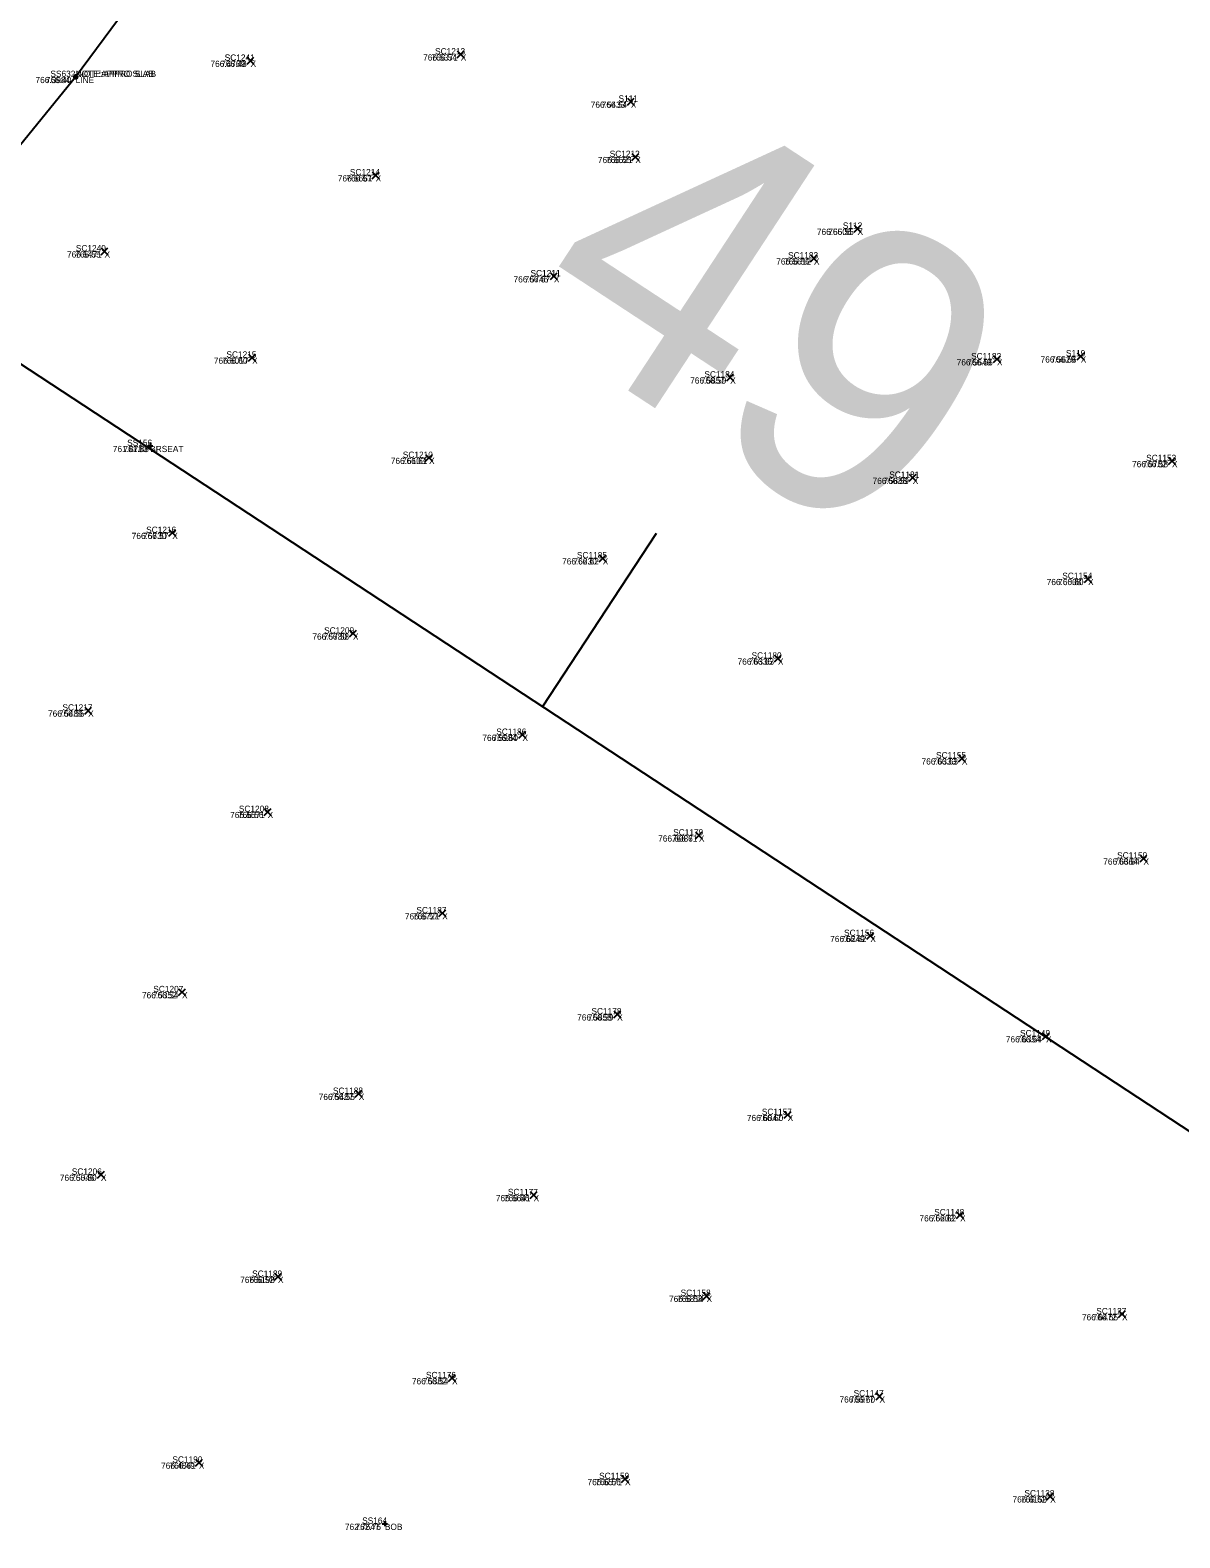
# Model space of a CAD drawing. Extents: x 1845019 to 1877956, y 680444 to 701081.
# Drawn here: x 1857559.96 to 1857571.05, y 694336.67 to 694351.2 of the extents above; entities that cross this region are included whole.
import ezdxf

# ---------------------------------------------------------------- set-up
doc = ezdxf.new("R2010")
doc.units = 0
for name, color, linetype in [('BR_X_SV_Beam_Seat', 7, 'Continuous'), ('BR_X_SV_Bottom_of_Beam_Text', 7, 'Continuous'), ('Default', 7, 'Continuous'), ('SV_X_CL_Survey_20', 7, 'Continuous'), ('SV_X_Random_Point', 7, 'Continuous'), ('SV_X_Shot_Marker', 7, 'Continuous'), ('SV_X_Text_Comment', 7, 'Continuous'), ('SV_X_Text_Description', 7, 'Continuous'), ('SV_X_Text_Elevation', 7, 'Continuous'), ('SV_X_Text_Name', 7, 'Continuous')]:
    doc.layers.add(name, color=color, linetype=linetype)

msp = doc.modelspace()

# ---------------------------------------------------------------- linework, layer by layer
at = {"layer": 'BR_X_SV_Beam_Seat'}
for p, q in [((1857561.092, 694347.198), (1857561.142, 694347.198)), ((1857561.092, 694347.198), (1857561.142, 694347.198)), ((1857561.117, 694347.223), (1857561.117, 694347.173)), ((1857561.117, 694347.223), (1857561.117, 694347.173)), ((1857561.117, 694347.198), (1857561.117, 694347.198)), ((1857561.117, 694347.198), (1857561.117, 694347.198))]:
    msp.add_line(p, q, dxfattribs=at)
at = {"layer": 'BR_X_SV_Bottom_of_Beam_Text'}
for p, q in [((1857563.355, 694336.811), (1857563.405, 694336.811)), ((1857563.355, 694336.811), (1857563.405, 694336.811)), ((1857563.38, 694336.836), (1857563.38, 694336.786)), ((1857563.38, 694336.836), (1857563.38, 694336.786)), ((1857563.38, 694336.811), (1857563.38, 694336.811)), ((1857563.38, 694336.811), (1857563.38, 694336.811))]:
    msp.add_line(p, q, dxfattribs=at)
at = {"layer": 'Default'}
msp.add_lwpolyline([(1857529.179, 694350.113), (1857549.875, 694336.9), (1857553.678, 694341.573), (1857557.829, 694347.6), (1857560.398, 694350.754), (1857568.363, 694361.498), (1857547.247, 694374.307), (1857542.393, 694367.435), (1857538.138, 694361.818), (1857529.244, 694350.474)], dxfattribs=at)
msp.add_lwpolyline([(1857529.179, 694350.113), (1857549.875, 694336.9), (1857553.678, 694341.573), (1857557.829, 694347.6), (1857560.398, 694350.754), (1857568.363, 694361.498), (1857547.247, 694374.307), (1857542.393, 694367.435), (1857538.138, 694361.818), (1857529.244, 694350.474)], dxfattribs=at)
at = {"layer": 'SV_X_CL_Survey_20'}
for p, q in [((1856038.267, 695346.314), (1858797.327, 693536.085)), ((1857564.901, 694344.684), (1857565.998, 694346.357))]:
    msp.add_line(p, q, dxfattribs=at)
at = {"layer": 'SV_X_Random_Point'}
for p, q in [((1857564.078, 694350.937), (1857564.145, 694351.004)), ((1857564.078, 694351.004), (1857564.145, 694350.937)), ((1857564.078, 694350.937), (1857564.145, 694351.004)), ((1857564.078, 694351.004), (1857564.145, 694350.937)), ((1857562.052, 694350.877), (1857562.118, 694350.943)), ((1857562.052, 694350.943), (1857562.118, 694350.877)), ((1857562.052, 694350.877), (1857562.118, 694350.943)), ((1857562.052, 694350.943), (1857562.118, 694350.877)), ((1857565.719, 694350.482), (1857565.785, 694350.549)), ((1857565.719, 694350.549), (1857565.785, 694350.482)), ((1857565.719, 694350.482), (1857565.785, 694350.549)), ((1857565.719, 694350.549), (1857565.785, 694350.482)), ((1857565.762, 694349.949), (1857565.829, 694350.016)), ((1857565.762, 694350.016), (1857565.829, 694349.949)), ((1857565.762, 694349.949), (1857565.829, 694350.016)), ((1857565.762, 694350.016), (1857565.829, 694349.949)), ((1857563.257, 694349.773), (1857563.324, 694349.839)), ((1857563.257, 694349.839), (1857563.324, 694349.773)), ((1857563.257, 694349.773), (1857563.324, 694349.839)), ((1857563.257, 694349.839), (1857563.324, 694349.773)), ((1857567.905, 694349.258), (1857567.971, 694349.325)), ((1857567.905, 694349.325), (1857567.971, 694349.258)), ((1857567.905, 694349.258), (1857567.971, 694349.325)), ((1857567.905, 694349.325), (1857567.971, 694349.258)), ((1857560.644, 694349.039), (1857560.71, 694349.106)), ((1857560.644, 694349.106), (1857560.71, 694349.039)), ((1857560.644, 694349.039), (1857560.71, 694349.106)), ((1857560.644, 694349.106), (1857560.71, 694349.039)), ((1857567.483, 694348.972), (1857567.55, 694349.038)), ((1857567.483, 694349.038), (1857567.55, 694348.972)), ((1857567.483, 694348.972), (1857567.55, 694349.038)), ((1857567.483, 694349.038), (1857567.55, 694348.972)), ((1857564.976, 694348.8), (1857565.043, 694348.867)), ((1857564.976, 694348.867), (1857565.043, 694348.8)), ((1857564.976, 694348.8), (1857565.043, 694348.867)), ((1857564.976, 694348.867), (1857565.043, 694348.8)), ((1857562.066, 694348.015), (1857562.133, 694348.082)), ((1857562.066, 694348.082), (1857562.133, 694348.015)), ((1857562.066, 694348.015), (1857562.133, 694348.082)), ((1857562.066, 694348.082), (1857562.133, 694348.015)), ((1857569.249, 694348), (1857569.315, 694348.067)), ((1857569.249, 694348.067), (1857569.315, 694348)), ((1857569.249, 694348), (1857569.315, 694348.067)), ((1857569.249, 694348.067), (1857569.315, 694348)), ((1857570.056, 694348.028), (1857570.123, 694348.094)), ((1857570.056, 694348.094), (1857570.123, 694348.028)), ((1857570.056, 694348.028), (1857570.123, 694348.094)), ((1857570.056, 694348.094), (1857570.123, 694348.028)), ((1857566.677, 694347.825), (1857566.743, 694347.891)), ((1857566.677, 694347.891), (1857566.743, 694347.825)), ((1857566.677, 694347.825), (1857566.743, 694347.891)), ((1857566.677, 694347.891), (1857566.743, 694347.825)), ((1857563.772, 694347.049), (1857563.839, 694347.116)), ((1857563.772, 694347.116), (1857563.839, 694347.049)), ((1857563.772, 694347.049), (1857563.839, 694347.116)), ((1857563.772, 694347.116), (1857563.839, 694347.049)), ((1857570.937, 694347.019), (1857571.003, 694347.085)), ((1857570.937, 694347.085), (1857571.003, 694347.019)), ((1857570.937, 694347.019), (1857571.003, 694347.085)), ((1857570.937, 694347.085), (1857571.003, 694347.019)), ((1857568.436, 694346.857), (1857568.503, 694346.924)), ((1857568.436, 694346.924), (1857568.503, 694346.857)), ((1857568.436, 694346.857), (1857568.503, 694346.924)), ((1857568.436, 694346.924), (1857568.503, 694346.857)), ((1857561.296, 694346.327), (1857561.363, 694346.393)), ((1857561.296, 694346.393), (1857561.363, 694346.327)), ((1857561.296, 694346.327), (1857561.363, 694346.393)), ((1857561.296, 694346.393), (1857561.363, 694346.327)), ((1857565.448, 694346.081), (1857565.514, 694346.148)), ((1857565.448, 694346.148), (1857565.514, 694346.081)), ((1857565.448, 694346.081), (1857565.514, 694346.148)), ((1857565.448, 694346.148), (1857565.514, 694346.081)), ((1857570.127, 694345.882), (1857570.194, 694345.949)), ((1857570.127, 694345.949), (1857570.194, 694345.882)), ((1857570.127, 694345.882), (1857570.194, 694345.949)), ((1857570.127, 694345.949), (1857570.194, 694345.882)), ((1857563.038, 694345.357), (1857563.105, 694345.423)), ((1857563.038, 694345.423), (1857563.105, 694345.357)), ((1857563.038, 694345.357), (1857563.105, 694345.423)), ((1857563.038, 694345.423), (1857563.105, 694345.357)), ((1857567.136, 694345.116), (1857567.203, 694345.182)), ((1857567.136, 694345.182), (1857567.203, 694345.116)), ((1857567.136, 694345.116), (1857567.203, 694345.182)), ((1857567.136, 694345.182), (1857567.203, 694345.116)), ((1857560.486, 694344.614), (1857560.552, 694344.681)), ((1857560.486, 694344.681), (1857560.552, 694344.614)), ((1857560.486, 694344.614), (1857560.552, 694344.681)), ((1857560.486, 694344.681), (1857560.552, 694344.614)), ((1857564.673, 694344.381), (1857564.74, 694344.447)), ((1857564.673, 694344.447), (1857564.74, 694344.381)), ((1857564.673, 694344.381), (1857564.74, 694344.447)), ((1857564.673, 694344.447), (1857564.74, 694344.381)), ((1857568.91, 694344.154), (1857568.977, 694344.221)), ((1857568.91, 694344.221), (1857568.977, 694344.154)), ((1857568.91, 694344.154), (1857568.977, 694344.221)), ((1857568.91, 694344.221), (1857568.977, 694344.154)), ((1857562.216, 694343.637), (1857562.283, 694343.704)), ((1857562.216, 694343.704), (1857562.283, 694343.637)), ((1857562.216, 694343.637), (1857562.283, 694343.704)), ((1857562.216, 694343.704), (1857562.283, 694343.637)), ((1857566.375, 694343.411), (1857566.441, 694343.478)), ((1857566.375, 694343.478), (1857566.441, 694343.411)), ((1857566.375, 694343.411), (1857566.441, 694343.478)), ((1857566.375, 694343.478), (1857566.441, 694343.411)), ((1857570.662, 694343.189), (1857570.729, 694343.255)), ((1857570.662, 694343.255), (1857570.729, 694343.189)), ((1857570.662, 694343.189), (1857570.729, 694343.255)), ((1857570.662, 694343.255), (1857570.729, 694343.189)), ((1857563.9, 694342.661), (1857563.967, 694342.727)), ((1857563.9, 694342.727), (1857563.967, 694342.661)), ((1857563.9, 694342.661), (1857563.967, 694342.727)), ((1857563.9, 694342.727), (1857563.967, 694342.661)), ((1857568.027, 694342.443), (1857568.094, 694342.509)), ((1857568.027, 694342.509), (1857568.094, 694342.443)), ((1857568.027, 694342.443), (1857568.094, 694342.509)), ((1857568.027, 694342.509), (1857568.094, 694342.443)), ((1857561.391, 694341.901), (1857561.458, 694341.967)), ((1857561.391, 694341.967), (1857561.458, 694341.901)), ((1857561.391, 694341.901), (1857561.458, 694341.967)), ((1857561.391, 694341.967), (1857561.458, 694341.901)), ((1857565.587, 694341.687), (1857565.654, 694341.753)), ((1857565.587, 694341.753), (1857565.654, 694341.687)), ((1857565.587, 694341.687), (1857565.654, 694341.753)), ((1857565.587, 694341.753), (1857565.654, 694341.687)), ((1857569.722, 694341.476), (1857569.788, 694341.543)), ((1857569.722, 694341.543), (1857569.788, 694341.476)), ((1857569.722, 694341.476), (1857569.788, 694341.543)), ((1857569.722, 694341.543), (1857569.788, 694341.476)), ((1857563.095, 694340.921), (1857563.161, 694340.988)), ((1857563.095, 694340.988), (1857563.161, 694340.921)), ((1857563.095, 694340.921), (1857563.161, 694340.988)), ((1857563.095, 694340.988), (1857563.161, 694340.921)), ((1857567.231, 694340.718), (1857567.298, 694340.784)), ((1857567.231, 694340.784), (1857567.298, 694340.718)), ((1857567.231, 694340.718), (1857567.298, 694340.784)), ((1857567.231, 694340.784), (1857567.298, 694340.718)), ((1857560.609, 694340.141), (1857560.675, 694340.208)), ((1857560.609, 694340.208), (1857560.675, 694340.141)), ((1857560.609, 694340.141), (1857560.675, 694340.208)), ((1857560.609, 694340.208), (1857560.675, 694340.141)), ((1857564.781, 694339.945), (1857564.848, 694340.012)), ((1857564.781, 694340.012), (1857564.848, 694339.945)), ((1857564.781, 694339.945), (1857564.848, 694340.012)), ((1857564.781, 694340.012), (1857564.848, 694339.945)), ((1857568.893, 694339.751), (1857568.96, 694339.817)), ((1857568.893, 694339.817), (1857568.96, 694339.751)), ((1857568.893, 694339.751), (1857568.96, 694339.817)), ((1857568.893, 694339.817), (1857568.96, 694339.751)), ((1857562.316, 694339.158), (1857562.382, 694339.225)), ((1857562.316, 694339.225), (1857562.382, 694339.158)), ((1857562.316, 694339.158), (1857562.382, 694339.225)), ((1857562.316, 694339.225), (1857562.382, 694339.158)), ((1857566.448, 694338.973), (1857566.515, 694339.04)), ((1857566.448, 694339.04), (1857566.515, 694338.973)), ((1857566.448, 694338.973), (1857566.515, 694339.04)), ((1857566.448, 694339.04), (1857566.515, 694338.973)), ((1857570.454, 694338.797), (1857570.521, 694338.864)), ((1857570.454, 694338.864), (1857570.521, 694338.797)), ((1857570.454, 694338.797), (1857570.521, 694338.864)), ((1857570.454, 694338.864), (1857570.521, 694338.797)), ((1857563.994, 694338.181), (1857564.061, 694338.248)), ((1857563.994, 694338.248), (1857564.061, 694338.181)), ((1857563.994, 694338.181), (1857564.061, 694338.248)), ((1857563.994, 694338.248), (1857564.061, 694338.181)), ((1857568.116, 694338.004), (1857568.183, 694338.071)), ((1857568.116, 694338.071), (1857568.183, 694338.004)), ((1857568.116, 694338.004), (1857568.183, 694338.071)), ((1857568.116, 694338.071), (1857568.183, 694338.004)), ((1857561.553, 694337.366), (1857561.62, 694337.433)), ((1857561.553, 694337.433), (1857561.62, 694337.366)), ((1857561.553, 694337.366), (1857561.62, 694337.433)), ((1857561.553, 694337.433), (1857561.62, 694337.366)), ((1857565.662, 694337.209), (1857565.729, 694337.276)), ((1857565.662, 694337.276), (1857565.729, 694337.209)), ((1857565.662, 694337.209), (1857565.729, 694337.276)), ((1857565.662, 694337.276), (1857565.729, 694337.209)), ((1857569.762, 694337.041), (1857569.829, 694337.108)), ((1857569.762, 694337.108), (1857569.829, 694337.041)), ((1857569.762, 694337.041), (1857569.829, 694337.108)), ((1857569.762, 694337.108), (1857569.829, 694337.041))]:
    msp.add_line(p, q, dxfattribs=at)
at = {"layer": 'SV_X_Shot_Marker'}
for p, q in [((1857560.373, 694350.754), (1857560.423, 694350.754)), ((1857560.379, 694350.77), (1857560.418, 694350.738)), ((1857560.383, 694350.734), (1857560.414, 694350.773)), ((1857560.398, 694350.779), (1857560.398, 694350.729)), ((1857560.398, 694350.754), (1857560.398, 694350.754)), ((1857560.398, 694350.754), (1857560.398, 694350.754))]:
    msp.add_line(p, q, dxfattribs=at)

# ---------------------------------------------------------------- texts
at = {"layer": 'BR_X_SV_Beam_Seat'}
for s, p in [('761.8783', (1857560.757, 694347.138)), ('761.88', (1857560.859, 694347.138)), ('SS156', (1857560.895, 694347.198)), ('SS156', (1857560.895, 694347.198)), ('BRSEAT', (1857561.117, 694347.138))]:
    msp.add_text(s, height=0.06, dxfattribs=at).set_placement(p)
at = {"layer": 'BR_X_SV_Bottom_of_Beam_Text'}
for s, p in [('762.7647', (1857562.995, 694336.751)), ('762.76', (1857563.097, 694336.751)), ('SS164', (1857563.161, 694336.811)), ('SS164', (1857563.161, 694336.811)), ('BOB', (1857563.38, 694336.751))]:
    msp.add_text(s, height=0.06, dxfattribs=at).set_placement(p)
at = {"layer": 'SV_X_CL_Survey_20'}
msp.add_text('49', height=2.8, rotation=326.731, dxfattribs=at).set_placement((1857564.639, 694348.444))
at = {"layer": 'SV_X_Text_Comment'}
for s, p in [('X', (1857564.112, 694350.911)), ('X', (1857562.085, 694350.85)), ('LINE', (1857560.398, 694350.694)), ('X', (1857565.752, 694350.456)), ('X', (1857565.795, 694349.923)), ('X', (1857563.291, 694349.746)), ('X', (1857567.938, 694349.231)), ('X', (1857560.677, 694349.013)), ('X', (1857567.517, 694348.945)), ('X', (1857565.01, 694348.773)), ('X', (1857562.1, 694347.989)), ('X', (1857569.282, 694347.973)), ('X', (1857570.09, 694348.001)), ('X', (1857566.71, 694347.798)), ('X', (1857563.806, 694347.023)), ('X', (1857570.97, 694346.992)), ('X', (1857568.47, 694346.831)), ('X', (1857561.33, 694346.3)), ('X', (1857565.481, 694346.055)), ('X', (1857570.161, 694345.856)), ('X', (1857563.072, 694345.33)), ('X', (1857567.17, 694345.089)), ('X', (1857560.519, 694344.588)), ('X', (1857564.707, 694344.354)), ('X', (1857568.944, 694344.127)), ('X', (1857562.25, 694343.611)), ('X', (1857566.408, 694343.384)), ('X', (1857570.695, 694343.162)), ('X', (1857563.933, 694342.634)), ('X', (1857568.061, 694342.416)), ('X', (1857561.424, 694341.874)), ('X', (1857565.62, 694341.66)), ('X', (1857569.755, 694341.449)), ('X', (1857563.128, 694340.894)), ('X', (1857567.264, 694340.691)), ('X', (1857560.642, 694340.115)), ('X', (1857564.814, 694339.918)), ('X', (1857568.927, 694339.724)), ('X', (1857562.349, 694339.131)), ('X', (1857566.482, 694338.947)), ('X', (1857570.488, 694338.77)), ('X', (1857564.028, 694338.154)), ('X', (1857568.15, 694337.978)), ('X', (1857561.586, 694337.34)), ('X', (1857565.696, 694337.182)), ('X', (1857569.796, 694337.015))]:
    msp.add_text(s, height=0.06, dxfattribs=at).set_placement(p)
at = {"layer": 'SV_X_Text_Description'}
for s in ['NOTE:APPRO SLAB', ' NOTE:APPRO SLAB']:
    msp.add_text(s, height=0.06, dxfattribs=at).set_placement((1857560.398, 694350.754))
at = {"layer": 'SV_X_Text_Elevation'}
for s, p in [('766.5371', (1857563.749, 694350.911)), ('766.54', (1857563.83, 694350.911)), ('766.4769', (1857561.698, 694350.85)), ('766.48', (1857561.802, 694350.85)), ('766.3984', (1857560.011, 694350.694)), ('766.40', (1857560.111, 694350.694)), ('766.5433', (1857565.365, 694350.456)), ('766.54', (1857565.471, 694350.456)), ('766.5521', (1857565.434, 694349.923)), ('766.55', (1857565.513, 694349.923)), ('766.5661', (1857562.926, 694349.746)), ('766.57', (1857563.009, 694349.746)), ('766.5508', (1857567.546, 694349.231)), ('766.55', (1857567.656, 694349.231)), ('766.5471', (1857560.315, 694349.013)), ('766.55', (1857560.395, 694349.013)), ('766.5612', (1857567.154, 694348.945)), ('766.56', (1857567.231, 694348.945)), ('766.5746', (1857564.621, 694348.773)), ('766.57', (1857564.728, 694348.773)), ('766.6017', (1857561.731, 694347.989)), ('766.60', (1857561.811, 694347.989)), ('766.5649', (1857568.894, 694347.973)), ('766.56', (1857568.996, 694347.973)), ('766.5629', (1857569.703, 694348.001)), ('766.56', (1857569.804, 694348.001)), ('766.5857', (1857566.324, 694347.798)), ('766.59', (1857566.427, 694347.798)), ('766.6103', (1857563.437, 694347.023)), ('766.61', (1857563.545, 694347.023)), ('766.5782', (1857570.585, 694346.992)), ('766.58', (1857570.687, 694346.992)), ('766.5888', (1857568.083, 694346.831)), ('766.59', (1857568.187, 694346.831)), ('766.5730', (1857560.939, 694346.3)), ('766.57', (1857561.048, 694346.3)), ('766.6230', (1857565.089, 694346.055)), ('766.62', (1857565.198, 694346.055)), ('766.6008', (1857569.762, 694345.856)), ('766.60', (1857569.872, 694345.856)), ('766.5780', (1857562.681, 694345.33)), ('766.58', (1857562.789, 694345.33)), ('766.6335', (1857566.781, 694345.089)), ('766.63', (1857566.887, 694345.089)), ('766.5489', (1857560.132, 694344.588)), ('766.55', (1857560.237, 694344.588)), ('766.5984', (1857564.32, 694344.354)), ('766.60', (1857564.418, 694344.354)), ('766.6333', (1857568.555, 694344.127)), ('766.63', (1857568.661, 694344.127)), ('766.5571', (1857561.888, 694343.611)), ('766.56', (1857561.964, 694343.611)), ('766.6087', (1857566.015, 694343.384)), ('766.61', (1857566.148, 694343.384)), ('766.6364', (1857570.307, 694343.162)), ('766.64', (1857570.413, 694343.162)), ('766.5721', (1857563.573, 694342.634)), ('766.57', (1857563.651, 694342.634)), ('766.6249', (1857567.674, 694342.416)), ('766.62', (1857567.778, 694342.416)), ('766.5352', (1857561.038, 694341.874)), ('766.54', (1857561.143, 694341.874)), ('766.5858', (1857565.234, 694341.66)), ('766.59', (1857565.338, 694341.66)), ('766.6354', (1857569.368, 694341.449)), ('766.64', (1857569.472, 694341.449)), ('766.5487', (1857562.742, 694340.894)), ('766.55', (1857562.846, 694340.894)), ('766.6047', (1857566.871, 694340.691)), ('766.60', (1857566.976, 694340.691)), ('766.5046', (1857560.246, 694340.115)), ('766.50', (1857560.355, 694340.115)), ('766.5641', (1857564.45, 694339.918)), ('766.56', (1857564.528, 694339.918)), ('766.6203', (1857568.535, 694339.724)), ('766.62', (1857568.644, 694339.724)), ('766.5198', (1857561.985, 694339.131)), ('766.52', (1857562.067, 694339.131)), ('766.5814', (1857566.12, 694338.947)), ('766.58', (1857566.199, 694338.947)), ('766.6472', (1857570.102, 694338.77)), ('766.65', (1857570.205, 694338.77)), ('766.5382', (1857563.641, 694338.154)), ('766.54', (1857563.746, 694338.154)), ('766.5977', (1857567.764, 694337.978)), ('766.60', (1857567.862, 694337.978)), ('766.4861', (1857561.222, 694337.34)), ('766.49', (1857561.303, 694337.34)), ('766.5571', (1857565.334, 694337.182)), ('766.56', (1857565.41, 694337.182)), ('766.6159', (1857569.432, 694337.015)), ('766.62', (1857569.513, 694337.015))]:
    msp.add_text(s, height=0.06, dxfattribs=at).set_placement(p)
at = {"layer": 'SV_X_Text_Name'}
for s, p in [('SC1241', (1857561.835, 694350.91)), ('SC1241', (1857561.836, 694350.91)), ('SC1213', (1857563.864, 694350.971)), ('SC1213', (1857563.864, 694350.971)), ('SS632', (1857560.155, 694350.754)), ('SS632', (1857560.155, 694350.754)), ('S111', (1857565.633, 694350.516)), ('S111', (1857565.633, 694350.516)), ('SC1212', (1857565.548, 694349.983)), ('SC1212', (1857565.548, 694349.983)), ('SC1214', (1857563.043, 694349.806)), ('SC1214', (1857563.043, 694349.806)), ('S112', (1857567.796, 694349.291)), ('S112', (1857567.796, 694349.291)), ('SC1240', (1857560.4, 694349.073)), ('SC1240', (1857560.4, 694349.073)), ('SC1183', (1857567.268, 694349.005)), ('SC1183', (1857567.268, 694349.005)), ('SC1211', (1857564.784, 694348.833)), ('SC1211', (1857564.785, 694348.833)), ('SC1215', (1857561.852, 694348.049)), ('SC1215', (1857561.852, 694348.049)), ('SC1182', (1857569.033, 694348.033)), ('SC1182', (1857569.033, 694348.033)), ('S119', (1857569.947, 694348.061)), ('S119', (1857569.947, 694348.061)), ('SC1184', (1857566.461, 694347.858)), ('SC1184', (1857566.461, 694347.858)), ('SC1210', (1857563.553, 694347.083)), ('SC1210', (1857563.553, 694347.083)), ('SC1153', (1857570.721, 694347.052)), ('SC1153', (1857570.721, 694347.052)), ('SC1181', (1857568.243, 694346.891)), ('SC1181', (1857568.244, 694346.891)), ('SC1216', (1857561.078, 694346.36)), ('SC1216', (1857561.078, 694346.36)), ('SC1185', (1857565.232, 694346.115)), ('SC1185', (1857565.232, 694346.115)), ('SC1154', (1857569.912, 694345.916)), ('SC1154', (1857569.912, 694345.916)), ('SC1209', (1857562.794, 694345.39)), ('SC1209', (1857562.794, 694345.39)), ('SC1180', (1857566.916, 694345.149)), ('SC1180', (1857566.916, 694345.149)), ('SC1217', (1857560.271, 694344.648)), ('SC1217', (1857560.271, 694344.648)), ('SC1186', (1857564.454, 694344.414)), ('SC1186', (1857564.454, 694344.414)), ('SC1155', (1857568.695, 694344.187)), ('SC1155', (1857568.695, 694344.187)), ('SC1208', (1857561.972, 694343.671)), ('SC1208', (1857561.972, 694343.671)), ('SC1179', (1857566.16, 694343.444)), ('SC1179', (1857566.16, 694343.444)), ('SC1150', (1857570.441, 694343.222)), ('SC1150', (1857570.441, 694343.222)), ('SC1187', (1857563.684, 694342.694)), ('SC1187', (1857563.684, 694342.694)), ('SC1156', (1857567.808, 694342.476)), ('SC1156', (1857567.808, 694342.476)), ('SC1207', (1857561.147, 694341.934)), ('SC1207', (1857561.147, 694341.934)), ('SC1178', (1857565.372, 694341.72)), ('SC1178', (1857565.372, 694341.72)), ('SC1149', (1857569.505, 694341.509)), ('SC1149', (1857569.505, 694341.509)), ('SC1188', (1857562.879, 694340.954)), ('SC1188', (1857562.879, 694340.954)), ('SC1157', (1857567.015, 694340.751)), ('SC1157', (1857567.015, 694340.751)), ('SC1206', (1857560.361, 694340.175)), ('SC1206', (1857560.361, 694340.175)), ('SC1177', (1857564.566, 694339.978)), ('SC1177', (1857564.566, 694339.978)), ('SC1148', (1857568.677, 694339.784)), ('SC1148', (1857568.677, 694339.784)), ('SC1189', (1857562.1, 694339.191)), ('SC1189', (1857562.1, 694339.191)), ('SC1158', (1857566.232, 694339.007)), ('SC1158', (1857566.232, 694339.007)), ('SC1127', (1857570.24, 694338.83)), ('SC1127', (1857570.24, 694338.83)), ('SC1176', (1857563.776, 694338.214)), ('SC1176', (1857563.776, 694338.214)), ('SC1147', (1857567.9, 694338.038)), ('SC1147', (1857567.9, 694338.038)), ('SC1190', (1857561.331, 694337.4)), ('SC1190', (1857561.331, 694337.4)), ('SC1159', (1857565.446, 694337.242)), ('SC1159', (1857565.446, 694337.242)), ('SC1128', (1857569.547, 694337.075)), ('SC1128', (1857569.547, 694337.075))]:
    msp.add_text(s, height=0.06, dxfattribs=at).set_placement(p)

doc.saveas('drawing.dxf')
